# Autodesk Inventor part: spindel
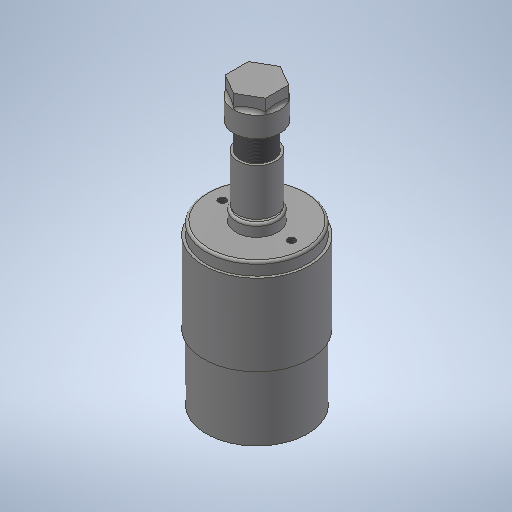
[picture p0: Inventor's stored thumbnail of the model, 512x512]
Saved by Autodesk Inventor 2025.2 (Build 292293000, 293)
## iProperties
Created: 2025-04
Part Number: spindel
Material: 1.0037 S235JR
Document SubType Name: Modeling
Designer: BennF
Density: 7.85 g/cm^3
Appearance: Stahl
Author: BennF
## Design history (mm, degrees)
sketch "Sketch2"
  geometry: L1 (21.2, 3.05)-(21.2, 30.75); L2 (21.2, 30.75)-(22.3, 30.75); L3 (22.3, 30.75)-(22.3, 64.75); L4 (22.3, 64.75)-(21.2, 64.75); L5 (21.2, 64.75)-(21.2, 70); L6 (21.2, 70)-(8.75, 70); L7 (8.75, 70)-(8.75, 75); L8 (8.75, 75)-(2.5, 75); L9 (0, 76)-(0, -6.5); L10 (21.2, 3.05)-(7.25, 3.05); L11 (7.25, 3.05)-(7.25, 0); L12 (7.25, 0)-(2.5, 0); L13 (2.5, 0)-(2.5, -6.5); L14 (2.5, -6.5)-(0, -6.5); L15 (2.5, 75)-(2.5, 76); L16 (2.5, 76)-(0, 76); 1 further point
  constraints: 33 end point, 12 perpendicular, 3 point on line, 1 horizontal, 1 horizontal alignment, 1 vertical, 1 vertical alignment
  dimensions: "d0" = 42.4 diameter of L1 L9; "d1" = 44.6 diameter of L3 L9; "d2" = 27.7 distance of L1.start L1.end; "d3" = 34 distance of L2.end L3.end; "d4" = 17.5 diameter of L7 L9; "d5" = 5.25 distance of L4.end L5.end; "d6" = 5 distance of L6.end L7.end; "d8" = 75 distance between parallel lines of L8 L12; "d9" = 14.5 diameter of L11 L9; "d10" = 5 diameter of L13 L9; "d11" = 6.5 distance of L12.end L13.end; "d12" = 1 distance of L8.end L15.end
revolve "Revolution1" sketch "Sketch2" stored, may be unused: angle "d7" = 90 deg
sketch "Sketch3"
  geometry: L1 (-2.5, 76)-(2.5, 76) reference; L2 (0, 76)-(8, 76); L3 (8, 76)-(8, 95.5); L4 (8, 95.5)-(7, 95.5); L5 (7, 95.5)-(7, 106.5); L6 (7, 106.5)-(0, 106.5); L7 (0, 106.5)-(0, 76); 1 further point
  constraints: 12 end point, 5 perpendicular, 1 midpoint, 1 point on line
  dimensions: "d13" = 16 diameter of L3 L7; "d14" = 14 diameter of L5 L7; "d15" = 19.5 distance of L2.end L3.end; "d16" = 11 distance of L4.end L5.end
revolve "Revolution2" sketch "Sketch3" stored, may be unused: angle "d17" = 90 deg
thread "Thread1" dims "d18" = 11, "d19" = 0
sketch "Sketch4"
  geometry: L1 (-7, 106.5)-(7, 106.5) reference; L2 (0, 106.5)-(9.75, 106.5); L3 (9.75, 106.5)-(9.75, 121); L4 (9.75, 121)-(0, 121); L5 (0, 121)-(0, 106.5); 2 further points
  constraints: 8 end point, 3 perpendicular, 1 horizontal, 1 midpoint
  dimensions: "d20" = 19.5 diameter of L3 L5; "d21" = 14.5 distance of L2.end L3.end
revolve "Revolution3" sketch "Sketch4" stored, may be unused: angle "d22" = 90 deg
sketch "Sketch5"
  geometry: L1 (0, 9.75)-(8.444, 4.875); L2 (8.444, 4.875)-(8.444, -4.875); L3 (8.444, -4.875)-(0, -9.75); L4 (0, -9.75)-(-8.444, -4.875); L5 (-8.444, -4.875)-(-8.444, 4.875); L6 (-8.444, 4.875)-(0, 9.75); 13 further points
  constraints: 12 end point, 1 coincident, 15 other
extrude "Extrusion1" cut sketch "Sketch5" distance "d23" = 6; taper "d24" = 0 deg
fillet "Fillet1" dims "d25" = 2
sketch "Sketch6"
  geometry: L1 (21.2, 70)-(21.2, 64.75) reference; L2 (21.2, 30.75)-(21.2, 3.05) reference; L3 (22.3, 64.75)-(22.3, 30.75) reference; L4 (22.3, 64.75)-(21.2, 64.75); L5 (21.2, 64.75)-(21.2, 30.75); L6 (22.3, 30.75)-(21.2, 30.75); L7 (-4.875, 121)-(4.875, 121) reference; L8 (0, 121)-(0, 0)
  constraints: 8 end point, 2 perpendicular, 1 horizontal, 1 midpoint, 1 vertical
revolve "Revolution4" sketch "Sketch6" stored, may be unused: angle "d26" = 30 deg
sketch "Sketch7"
  geometry: A1 r 14.5 centre (0, 0) between (14.5, 0) and (-14.5, 0); 1 further point
  constraints: 2 horizontal alignment, 2 point on circle, 1 centre point, 1 coincident
  dimensions: "d34" = 29 diameter of A1
hole "Hole1" sketch "Sketch7" at (14.5, 0), (-14.5, 0) diameter "d27" = 3.242; stored, may be unused: countersink angle "d31" = 90 deg, drill point angle "d33" = 0 deg; dims "d28" = 3, "d29" = 4, "d30" = 2, "d32" = 3
fillet "Fillet2" dims "d35" = 1
body "Solid1"
